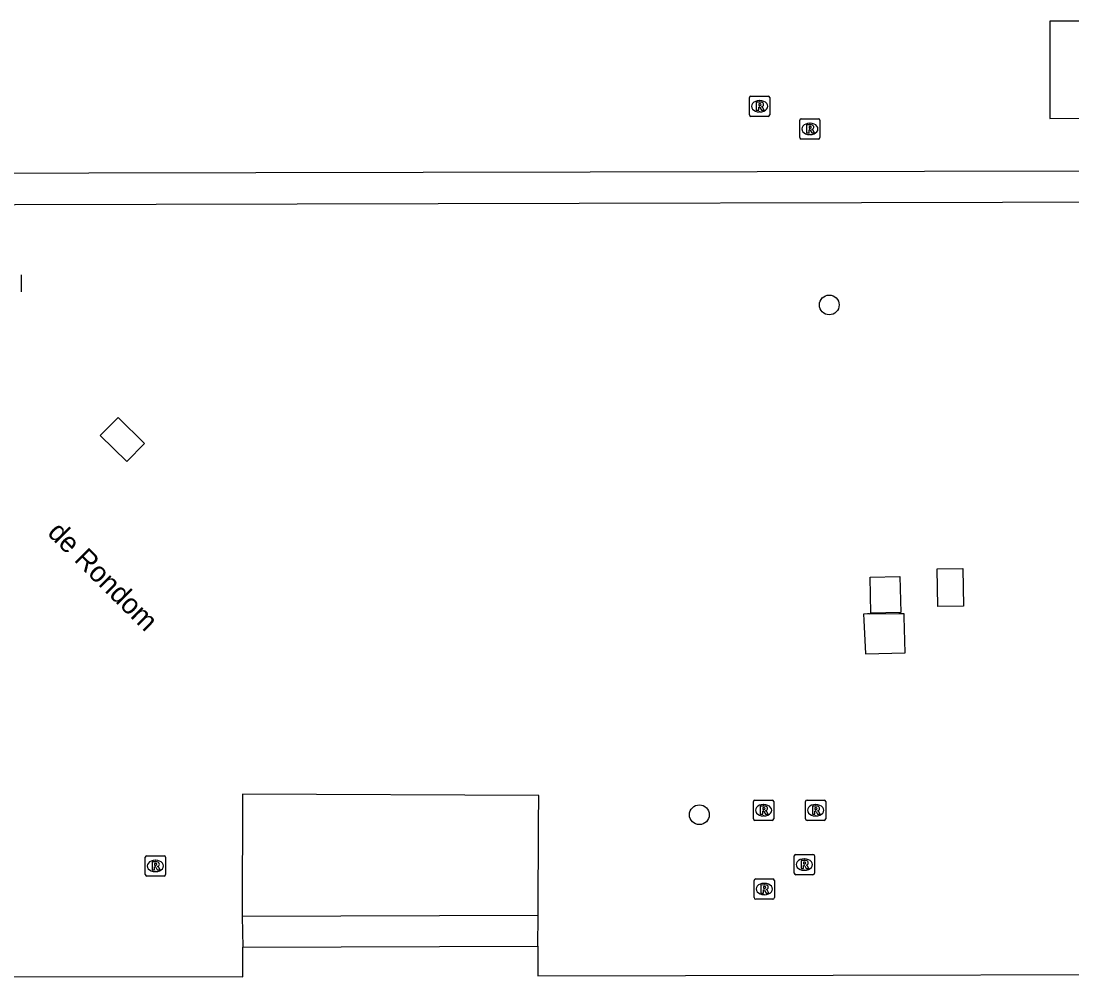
# Model space of a CAD drawing. Extents: x 161477 to 163040, y 383680 to 384868.
# Drawn here: x 162177.9 to 162229.8, y 384190.9 to 384238.1 of the extents above; entities that cross this region are included whole.
import ezdxf

# ---------------------------------------------------------------- set-up
doc = ezdxf.new("R2010")
doc.units = 0
for name, color, linetype in [('IMGEO_Boom', 7, 'Continuous'), ('IMGEO_Groenvoorziening', 7, 'Continuous'), ('IMGEO_Lage_trafo', 7, 'Continuous'), ('IMGEO_Openbare_ruimte_label', 7, 'Continuous'), ('IMGEO_Rioolput', 7, 'Continuous'), ('IMGEO_Voetpad_open', 7, 'Continuous')]:
    doc.layers.add(name, color=color, linetype=linetype)

msp = doc.modelspace()

# ---------------------------------------------------------------- linework, layer by layer
at = {"layer": 'IMGEO_Boom'}
for centre in [(162217.856, 384224.116), (162211.437, 384198.917)]:
    msp.add_circle(centre, 0.489, dxfattribs=at)
at = {"layer": 'IMGEO_Groenvoorziening'}
msp.add_lwpolyline([(162221.561, 384208.694), (162221.557, 384208.855), (162221.302, 384208.85), (162219.839, 384208.823), (162219.838, 384208.846), (162219.749, 384208.842), (162219.55, 384208.831), (162219.565, 384208.532), (162219.649, 384206.867), (162221.605, 384206.913), (162221.561, 384208.694)], dxfattribs=at)
at = {"layer": 'IMGEO_Lage_trafo'}
for points in [[(162182.716, 384218.554), (162184.021, 384217.263), (162183.142, 384216.374), (162181.837, 384217.665), (162182.716, 384218.554)], [(162223.193, 384211.077), (162224.462, 384211.093), (162224.484, 384209.231), (162223.215, 384209.215), (162223.193, 384211.077)], [(162219.879, 384210.656), (162221.349, 384210.687), (162221.386, 384208.918), (162219.916, 384208.887), (162219.879, 384210.656)]]:
    msp.add_lwpolyline(points, dxfattribs=at)
at = {"layer": 'IMGEO_Rioolput'}
for p, q in [((162213.914, 384233.506), (162213.914, 384234.358)), ((162213.989, 384234.432), (162214.841, 384234.432)), ((162214.402, 384234.212), (162214.427, 384234.212)), ((162214.915, 384234.358), (162214.915, 384233.506)), ((162214.425, 384233.652), (162214.4, 384233.652)), ((162214.841, 384233.432), (162213.989, 384233.432)), ((162216.397, 384232.386), (162216.397, 384233.238)), ((162216.472, 384233.312), (162217.324, 384233.312)), ((162216.885, 384233.092), (162216.91, 384233.092)), ((162217.398, 384233.238), (162217.398, 384232.386)), ((162217.324, 384232.312), (162216.472, 384232.312)), ((162216.908, 384232.532), (162216.883, 384232.532)), ((162177.92, 384225.606), (162177.92, 384224.754)), ((162214.109, 384198.715), (162214.109, 384199.567)), ((162214.184, 384199.641), (162215.036, 384199.641)), ((162214.597, 384199.421), (162214.622, 384199.421)), ((162215.11, 384199.567), (162215.11, 384198.715)), ((162216.683, 384198.715), (162216.683, 384199.567)), ((162216.758, 384199.641), (162217.61, 384199.641)), ((162217.171, 384199.421), (162217.196, 384199.421)), ((162217.684, 384199.567), (162217.684, 384198.715)), ((162214.62, 384198.861), (162214.595, 384198.861)), ((162217.194, 384198.861), (162217.169, 384198.861)), ((162215.036, 384198.641), (162214.184, 384198.641)), ((162217.61, 384198.641), (162216.758, 384198.641)), ((162184.06, 384195.963), (162184.06, 384196.815)), ((162184.135, 384196.889), (162184.987, 384196.889)), ((162185.061, 384196.815), (162185.061, 384195.963)), ((162216.124, 384196.03), (162216.124, 384196.882)), ((162216.199, 384196.956), (162217.051, 384196.956)), ((162216.612, 384196.736), (162216.637, 384196.736)), ((162217.125, 384196.882), (162217.125, 384196.03)), ((162184.548, 384196.669), (162184.573, 384196.669)), ((162184.987, 384195.889), (162184.135, 384195.889)), ((162184.571, 384196.109), (162184.546, 384196.109)), ((162214.145, 384194.822), (162214.145, 384195.674)), ((162214.22, 384195.748), (162215.072, 384195.748)), ((162215.146, 384195.674), (162215.146, 384194.822)), ((162217.051, 384195.956), (162216.199, 384195.956)), ((162216.635, 384196.176), (162216.61, 384196.176)), ((162214.633, 384195.528), (162214.658, 384195.528)), ((162215.072, 384194.748), (162214.22, 384194.748)), ((162214.656, 384194.968), (162214.631, 384194.968))]:
    msp.add_line(p, q, dxfattribs=at)
for points in [[(162213.914, 384233.506), (162213.914, 384234.358)], [(162213.989, 384234.432), (162214.841, 384234.432)], [(162214.503, 384234.13), (162214.251, 384234.132), (162214.251, 384233.732)], [(162214.915, 384234.358), (162214.915, 384233.506)], [(162214.251, 384233.732), (162214.375, 384233.732), (162214.375, 384233.894), (162214.386, 384233.894)], [(162214.429, 384234.051), (162214.375, 384234.051), (162214.375, 384233.97)], [(162214.375, 384233.97), (162214.427, 384233.97)], [(162214.433, 384233.865), (162214.504, 384233.732), (162214.644, 384233.732), (162214.579, 384233.858)], [(162214.841, 384233.432), (162213.989, 384233.432)], [(162216.397, 384232.386), (162216.397, 384233.238)], [(162216.472, 384233.312), (162217.324, 384233.312)], [(162217.398, 384233.238), (162217.398, 384232.386)], [(162216.986, 384233.01), (162216.734, 384233.012), (162216.734, 384232.612)], [(162216.734, 384232.612), (162216.858, 384232.612), (162216.858, 384232.774), (162216.869, 384232.774)], [(162216.912, 384232.931), (162216.858, 384232.931), (162216.858, 384232.85)], [(162216.858, 384232.85), (162216.91, 384232.85)], [(162216.916, 384232.745), (162216.987, 384232.612), (162217.127, 384232.612), (162217.062, 384232.738)], [(162217.324, 384232.312), (162216.472, 384232.312)], [(162177.92, 384225.606), (162177.92, 384224.754)], [(162214.109, 384198.715), (162214.109, 384199.567)], [(162214.184, 384199.641), (162215.036, 384199.641)], [(162214.698, 384199.339), (162214.446, 384199.341), (162214.446, 384198.941)], [(162215.11, 384199.567), (162215.11, 384198.715)], [(162216.683, 384198.715), (162216.683, 384199.567)], [(162216.758, 384199.641), (162217.61, 384199.641)], [(162217.272, 384199.339), (162217.02, 384199.341), (162217.02, 384198.941)], [(162217.684, 384199.567), (162217.684, 384198.715)], [(162214.446, 384198.941), (162214.57, 384198.941), (162214.57, 384199.103), (162214.581, 384199.103)], [(162214.624, 384199.26), (162214.57, 384199.26), (162214.57, 384199.179)], [(162214.57, 384199.179), (162214.622, 384199.179)], [(162214.628, 384199.074), (162214.699, 384198.941), (162214.839, 384198.941), (162214.774, 384199.067)], [(162217.02, 384198.941), (162217.144, 384198.941), (162217.144, 384199.103), (162217.155, 384199.103)], [(162217.198, 384199.26), (162217.144, 384199.26), (162217.144, 384199.179)], [(162217.144, 384199.179), (162217.196, 384199.179)], [(162217.202, 384199.074), (162217.273, 384198.941), (162217.413, 384198.941), (162217.348, 384199.067)], [(162215.036, 384198.641), (162214.184, 384198.641)], [(162217.61, 384198.641), (162216.758, 384198.641)], [(162184.06, 384195.963), (162184.06, 384196.815)], [(162184.135, 384196.889), (162184.987, 384196.889)], [(162185.061, 384196.815), (162185.061, 384195.963)], [(162216.124, 384196.03), (162216.124, 384196.882)], [(162216.199, 384196.956), (162217.051, 384196.956)], [(162217.125, 384196.882), (162217.125, 384196.03)], [(162184.649, 384196.587), (162184.397, 384196.589), (162184.397, 384196.189)], [(162184.397, 384196.189), (162184.521, 384196.189), (162184.521, 384196.351), (162184.532, 384196.351)], [(162184.575, 384196.508), (162184.521, 384196.508), (162184.521, 384196.427)], [(162184.521, 384196.427), (162184.573, 384196.427)], [(162184.579, 384196.322), (162184.65, 384196.189), (162184.79, 384196.189), (162184.725, 384196.315)], [(162216.713, 384196.654), (162216.461, 384196.656), (162216.461, 384196.256)], [(162216.461, 384196.256), (162216.585, 384196.256), (162216.585, 384196.418), (162216.596, 384196.418)], [(162216.639, 384196.575), (162216.585, 384196.575), (162216.585, 384196.494)], [(162216.585, 384196.494), (162216.637, 384196.494)], [(162216.643, 384196.389), (162216.714, 384196.256), (162216.854, 384196.256), (162216.789, 384196.382)], [(162184.987, 384195.889), (162184.135, 384195.889)], [(162214.145, 384194.822), (162214.145, 384195.674)], [(162214.22, 384195.748), (162215.072, 384195.748)], [(162215.146, 384195.674), (162215.146, 384194.822)], [(162217.051, 384195.956), (162216.199, 384195.956)], [(162214.734, 384195.446), (162214.482, 384195.448), (162214.482, 384195.048)], [(162214.482, 384195.048), (162214.606, 384195.048), (162214.606, 384195.21), (162214.617, 384195.21)], [(162214.66, 384195.367), (162214.606, 384195.367), (162214.606, 384195.286)], [(162214.606, 384195.286), (162214.658, 384195.286)], [(162214.664, 384195.181), (162214.735, 384195.048), (162214.875, 384195.048), (162214.81, 384195.174)], [(162215.072, 384194.748), (162214.22, 384194.748)]]:
    msp.add_lwpolyline(points, dxfattribs=at)
for centre, radius, start, end in [((162213.991, 384234.356), 0.0765, 91.552, 178.448), ((162213.991, 384234.356), 0.0765, 91.552, 178.448), ((162214.502, 384234.02), 0.109, 350.3612, 89.416), ((162214.839, 384234.356), 0.0765, 1.552, 88.448), ((162214.839, 384234.356), 0.0765, 1.552, 88.448), ((162214.385, 384233.841), 0.0533, 26.0293, 88.6989), ((162214.411, 384234.159), 0.19, 274.7715, 282.9687), ((162214.435, 384233.955), 0.0964, 77.0061, 93.1865), ((162214.449, 384234.012), 0.0378, 276.6634, 79.6772), ((162214.5, 384234.02), 0.112, 277.5842, 350.9817), ((162214.484, 384233.805), 0.108, 29.5134, 73.7905), ((162213.991, 384233.508), 0.0765, 181.552, 268.448), ((162213.991, 384233.508), 0.0765, 181.552, 268.448), ((162214.839, 384233.508), 0.0765, 271.552, 358.448), ((162214.839, 384233.508), 0.0765, 271.552, 358.448), ((162216.474, 384233.236), 0.0765, 91.552, 178.448), ((162216.474, 384233.236), 0.0765, 91.552, 178.448), ((162217.322, 384233.236), 0.0765, 1.552, 88.448), ((162217.322, 384233.236), 0.0765, 1.552, 88.448), ((162216.868, 384232.721), 0.0533, 26.0293, 88.6989), ((162216.894, 384233.039), 0.19, 274.7715, 282.9687), ((162216.918, 384232.835), 0.0964, 77.0061, 93.1865), ((162216.932, 384232.892), 0.0378, 276.6634, 79.6772), ((162216.985, 384232.9), 0.109, 350.3612, 89.416), ((162216.983, 384232.9), 0.112, 277.5842, 350.9817), ((162216.967, 384232.685), 0.108, 29.5134, 73.7905), ((162216.474, 384232.388), 0.0765, 181.552, 268.448), ((162216.474, 384232.388), 0.0765, 181.552, 268.448), ((162217.322, 384232.388), 0.0765, 271.552, 358.448), ((162217.322, 384232.388), 0.0765, 271.552, 358.448), ((162214.186, 384199.565), 0.0765, 91.552, 178.448), ((162214.186, 384199.565), 0.0765, 91.552, 178.448), ((162214.697, 384199.229), 0.109, 350.3612, 89.416), ((162215.034, 384199.565), 0.0765, 1.552, 88.448), ((162215.034, 384199.565), 0.0765, 1.552, 88.448), ((162216.76, 384199.565), 0.0765, 91.552, 178.448), ((162216.76, 384199.565), 0.0765, 91.552, 178.448), ((162217.271, 384199.229), 0.109, 350.3612, 89.416), ((162217.608, 384199.565), 0.0765, 1.552, 88.448), ((162217.608, 384199.565), 0.0765, 1.552, 88.448), ((162214.58, 384199.05), 0.0533, 26.0293, 88.6989), ((162214.606, 384199.368), 0.19, 274.7715, 282.9687), ((162214.63, 384199.164), 0.0964, 77.0061, 93.1865), ((162214.644, 384199.221), 0.0378, 276.6634, 79.6772), ((162214.695, 384199.229), 0.112, 277.5842, 350.9817), ((162214.679, 384199.014), 0.108, 29.5134, 73.7905), ((162217.154, 384199.05), 0.0533, 26.0293, 88.6989), ((162217.18, 384199.368), 0.19, 274.7715, 282.9687), ((162217.204, 384199.164), 0.0964, 77.0061, 93.1865), ((162217.218, 384199.221), 0.0378, 276.6634, 79.6772), ((162217.269, 384199.229), 0.112, 277.5842, 350.9817), ((162217.253, 384199.014), 0.108, 29.5134, 73.7905), ((162214.186, 384198.717), 0.0765, 181.552, 268.448), ((162214.186, 384198.717), 0.0765, 181.552, 268.448), ((162215.034, 384198.717), 0.0765, 271.552, 358.448), ((162215.034, 384198.717), 0.0765, 271.552, 358.448), ((162216.76, 384198.717), 0.0765, 181.552, 268.448), ((162216.76, 384198.717), 0.0765, 181.552, 268.448), ((162217.608, 384198.717), 0.0765, 271.552, 358.448), ((162217.608, 384198.717), 0.0765, 271.552, 358.448), ((162184.137, 384196.813), 0.0765, 91.552, 178.448), ((162184.137, 384196.813), 0.0765, 91.552, 178.448), ((162184.985, 384196.813), 0.0765, 1.552, 88.448), ((162184.985, 384196.813), 0.0765, 1.552, 88.448), ((162216.201, 384196.88), 0.0765, 91.552, 178.448), ((162216.201, 384196.88), 0.0765, 91.552, 178.448), ((162217.049, 384196.88), 0.0765, 1.552, 88.448), ((162217.049, 384196.88), 0.0765, 1.552, 88.448), ((162184.531, 384196.298), 0.0533, 26.0293, 88.6989), ((162184.557, 384196.616), 0.19, 274.7715, 282.9687), ((162184.581, 384196.412), 0.0964, 77.0061, 93.1865), ((162184.595, 384196.469), 0.0378, 276.6634, 79.6772), ((162184.648, 384196.477), 0.109, 350.3612, 89.416), ((162184.646, 384196.477), 0.112, 277.5842, 350.9817), ((162184.63, 384196.262), 0.108, 29.5134, 73.7905), ((162216.595, 384196.365), 0.0533, 26.0293, 88.6989), ((162216.621, 384196.683), 0.19, 274.7715, 282.9687), ((162216.645, 384196.479), 0.0964, 77.0061, 93.1865), ((162216.659, 384196.536), 0.0378, 276.6634, 79.6772), ((162216.712, 384196.544), 0.109, 350.3612, 89.416), ((162216.71, 384196.544), 0.112, 277.5842, 350.9817), ((162216.694, 384196.329), 0.108, 29.5134, 73.7905), ((162184.137, 384195.965), 0.0765, 181.552, 268.448), ((162184.137, 384195.965), 0.0765, 181.552, 268.448), ((162184.985, 384195.965), 0.0765, 271.552, 358.448), ((162184.985, 384195.965), 0.0765, 271.552, 358.448), ((162214.222, 384195.672), 0.0765, 91.552, 178.448), ((162214.222, 384195.672), 0.0765, 91.552, 178.448), ((162215.07, 384195.672), 0.0765, 1.552, 88.448), ((162215.07, 384195.672), 0.0765, 1.552, 88.448), ((162216.201, 384196.032), 0.0765, 181.552, 268.448), ((162216.201, 384196.032), 0.0765, 181.552, 268.448), ((162217.049, 384196.032), 0.0765, 271.552, 358.448), ((162217.049, 384196.032), 0.0765, 271.552, 358.448), ((162214.616, 384195.157), 0.0533, 26.0293, 88.6989), ((162214.642, 384195.475), 0.19, 274.7715, 282.9687), ((162214.666, 384195.271), 0.0964, 77.0061, 93.1865), ((162214.68, 384195.328), 0.0378, 276.6634, 79.6772), ((162214.733, 384195.336), 0.109, 350.3612, 89.416), ((162214.731, 384195.336), 0.112, 277.5842, 350.9817), ((162214.715, 384195.121), 0.108, 29.5134, 73.7905), ((162214.222, 384194.824), 0.0765, 181.552, 268.448), ((162214.222, 384194.824), 0.0765, 181.552, 268.448), ((162215.07, 384194.824), 0.0765, 271.552, 358.448), ((162215.07, 384194.824), 0.0765, 271.552, 358.448)]:
    msp.add_arc(centre, radius, start, end, dxfattribs=at)
for centre, major_axis, ratio, start_param, end_param in [((162214.401, 384233.932), (-0.387, 0.002), 0.722429, 4.712389, 7.853982), ((162214.426, 384233.932), (-0.39, 0.002), 0.717154, 1.570796, 4.712389), ((162216.884, 384232.812), (-0.387, 0.002), 0.722429, 4.712389, 7.853982), ((162216.909, 384232.812), (-0.39, 0.002), 0.717154, 1.570796, 4.712389), ((162214.596, 384199.141), (-0.387, 0.002), 0.722429, 4.712389, 7.853982), ((162214.621, 384199.141), (-0.39, 0.002), 0.717154, 1.570796, 4.712389), ((162217.17, 384199.141), (-0.387, 0.002), 0.722429, 4.712389, 7.853982), ((162217.195, 384199.141), (-0.39, 0.002), 0.717154, 1.570796, 4.712389), ((162216.611, 384196.456), (-0.387, 0.002), 0.722429, 4.712389, 7.853982), ((162216.636, 384196.456), (-0.39, 0.002), 0.717154, 1.570796, 4.712389), ((162184.547, 384196.389), (-0.387, 0.002), 0.722429, 4.712389, 7.853982), ((162184.572, 384196.389), (-0.39, 0.002), 0.717154, 1.570796, 4.712389), ((162214.632, 384195.248), (-0.387, 0.002), 0.722429, 4.712389, 7.853982), ((162214.657, 384195.248), (-0.39, 0.002), 0.717154, 1.570796, 4.712389)]:
    msp.add_ellipse(centre, major_axis=major_axis, ratio=ratio, start_param=start_param, end_param=end_param, dxfattribs=at)
at = {"layer": 'IMGEO_Voetpad_open'}
for points in [[(162233.585, 384238.132), (162228.753, 384238.146), (162228.753, 384233.335), (162233.593, 384233.368), (162233.585, 384238.132)], [(162247.31, 384229.25), (162247.326, 384230.758), (162106.918, 384230.479), (162106.909, 384230.479), (162106.921, 384228.996)], [(162106.921, 384228.996), (162177.63, 384229.082), (162247.31, 384229.25)], [(162203.472, 384193.943), (162203.493, 384198.466), (162203.5, 384199.866), (162188.858, 384199.942), (162188.85, 384193.884)], [(162203.472, 384193.943), (162188.85, 384193.884)], [(162188.85, 384193.884), (162188.873, 384192.38)], [(162203.457, 384192.425), (162203.472, 384193.943)], [(162104.654, 384191.016), (162188.881, 384190.9), (162188.873, 384192.38)], [(162188.873, 384192.38), (162203.457, 384192.425)], [(162203.457, 384192.425), (162203.464, 384190.959), (162247.212, 384191.051)]]:
    msp.add_lwpolyline(points, dxfattribs=at)

# ---------------------------------------------------------------- texts
at = {"layer": 'IMGEO_Openbare_ruimte_label'}
msp.add_text('de Rondom', height=1, rotation=315.081, dxfattribs=at).set_placement((162179.179, 384212.799))

doc.saveas('drawing.dxf')
